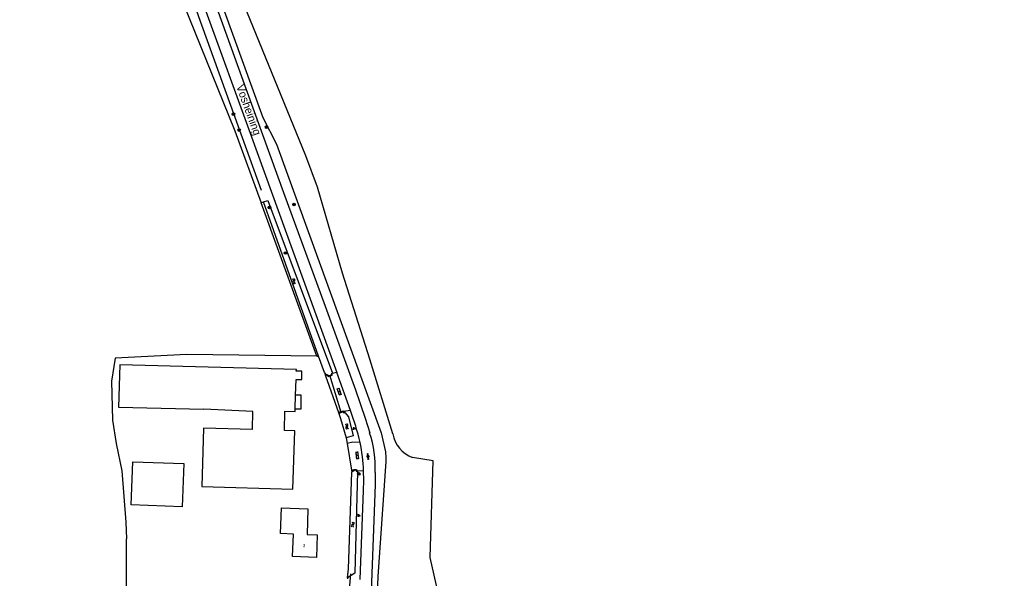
# Model space of a CAD drawing. Extents: x 124000 to 129000, y 395500 to 397503.
# Drawn here: x 125297.3 to 125607.1, y 396007.3 to 396181.7 of the extents above; entities that cross this region are included whole.
import ezdxf

# ---------------------------------------------------------------- set-up
doc = ezdxf.new("R2010")
doc.units = 0
for name, color, linetype in [('gg-afsc-hekwerk', 7, 'Continuous'), ('gg-anno-huisnummerreeks BGT', 7, 'Continuous'), ('gg-anno-openbare ruimte label', 7, 'Continuous'), ('gg-bbg-bijgebouw', 7, 'Continuous'), ('gg-bbg-gedigitaliseerde bijgebouw', 7, 'Continuous'), ('gg-bbg-hoofdgebouw', 7, 'Continuous'), ('gg-bbg-luifel en loopbrug', 7, 'Continuous'), ('gg-knt-bronhoudergrens', 7, 'Continuous'), ('gg-knt-verharding', 7, 'Continuous'), ('gg-kntw-bovenkant insteek waterloop', 7, 'Continuous'), ('gg-kntw-midden sloot', 7, 'Continuous'), ('gg-kwrk-duiker nz buis', 7, 'Continuous'), ('gg-kwrk-uitstroombak niveau min 01', 7, 'Continuous'), ('gt-grn-groengrens', 7, 'Continuous'), ('gt-grn-weggrens', 7, 'Continuous'), ('gt-symb-boom', 7, 'Continuous'), ('gt-symb-gesloten verharding', 7, 'Continuous'), ('gt-symb-groenvak', 7, 'Continuous'), ('gt-symb-klinker verharding', 7, 'Continuous'), ('gt-symb-watersymbool', 7, 'Continuous')]:
    doc.layers.add(name, color=color, linetype=linetype)

# ---------------------------------------------------------------- blocks, each defined once
blk = doc.blocks.new('gt0-BOOM')
at = {"layer": 'gt-symb-boom'}
for radius in [0.4, 0.2]:
    blk.add_circle((0, 0), radius, dxfattribs=at)
blk = doc.blocks.new('gt0-WA')
at = {"layer": 'gt-symb-watersymbool'}
for centre, start, end in [((-0.32, 0.02), 28.0725, 151.9275), ((0.43, 0.42), 208.0725, 331.9275), ((-0.32, -0.43), 28.0725, 151.9275), ((0.43, -0.03), 208.0725, 331.9275)]:
    blk.add_arc(centre, 0.425, start, end, dxfattribs=at)
blk = doc.blocks.new('gt0-KL1')
at = {"layer": 'gt-symb-klinker verharding'}
for p, q in [((-1.15, 0.3), (1.15, 0.3)), ((-1, -0.3), (-1, 0.3)), ((-0.5, 0.3), (-0.5, 0.45)), ((0, -0.3), (0, 0.3)), ((0.5, 0.3), (0.5, 0.45)), ((1, -0.3), (1, 0.3)), ((-1.15, -0.3), (1.15, -0.3)), ((-0.5, -0.45), (-0.5, -0.3)), ((0.5, -0.45), (0.5, -0.3))]:
    blk.add_line(p, q, dxfattribs=at)
blk = doc.blocks.new('gt0-GESVH1')
at = {"layer": 'gt-symb-gesloten verharding'}
for p, q in [((-0.99, -0.26), (0.01, 0.24)), ((0.01, -0.26), (-0.99, 0.24)), ((0.01, 0.24), (1.01, -0.26)), ((1.01, 0.24), (0.01, -0.26))]:
    blk.add_line(p, q, dxfattribs=at)
blk = doc.blocks.new('gt0-GRVAK')
at = {"layer": 'gt-symb-groenvak'}
for p, q in [((-0.11, 0.19), (-0.23, 0.24)), ((-0.18, 0.15), (0.09, 0.15)), ((-0.09, 0.21), (-0.16, 0.32)), ((-0.05, 0.21), (-0.05, 0.39)), ((0, 0.21), (0.06, 0.32)), ((0.01, 0.19), (0.13, 0.24)), ((0.26, -0.05), (0.2, 0.06)), ((0.3, -0.05), (0.3, 0.13)), ((0.35, -0.05), (0.41, 0.06)), ((-0.25, -0.23), (-0.36, -0.18)), ((-0.32, -0.26), (-0.05, -0.26)), ((-0.23, -0.21), (-0.29, -0.09)), ((-0.18, -0.2), (-0.18, -0.02)), ((-0.14, -0.21), (-0.07, -0.09)), ((-0.12, -0.23), (0, -0.18)), ((0.24, -0.07), (0.12, -0.02)), ((0.17, -0.11), (0.44, -0.11)), ((0.37, -0.07), (0.49, -0.02))]:
    blk.add_line(p, q, dxfattribs=at)

msp = doc.modelspace()

# ---------------------------------------------------------------- linework, layer by layer
at = {"layer": 'gg-afsc-hekwerk'}
for points in [[(125522.53, 396395.86), (125323.08, 396320.05), (125317.12, 396305.83), (125373.18, 396151.15), (125377.47, 396142.84), (125410.13, 396052.73), (125411.5, 396046.76), (125411.55, 396044.93)], [(125411.55, 396044.93), (125411.59, 396043.72), (125409.06, 396007.83), (125408.72, 396000)], [(125411.55, 396044.93), (125411.59, 396043.72), (125409.06, 396007.83), (125408.72, 396000)]]:
    msp.add_lwpolyline(points, dxfattribs=at)
at = {"layer": 'gg-bbg-bijgebouw'}
msp.add_line((125383.28, 396060.21), (125383.4, 396064.41), dxfattribs=at)
for points in [[(125383.4, 396064.41), (125383.54, 396069.33), (125385.32, 396069.3), (125385.37, 396071.91), (125383.61, 396071.94), (125383.62, 396072.48)], [(125382.54, 396035.08), (125383.12, 396053.31), (125379.88, 396053.41), (125380.01, 396059.41), (125383.25, 396059.31), (125383.28, 396060.21)]]:
    msp.add_lwpolyline(points, dxfattribs=at)
at = {"layer": 'gg-bbg-gedigitaliseerde bijgebouw'}
for p, q in [((125370.07, 396059.4), (125354.78, 396060.04)), ((125369.89, 396053.72), (125370.07, 396059.4)), ((125369.89, 396053.72), (125354.61, 396054.19))]:
    msp.add_line(p, q, dxfattribs=at)
for points in [[(125383.62, 396072.48), (125328.46, 396073.92), (125328.12, 396060.7), (125354.78, 396060.04)], [(125354.61, 396054.19), (125354.09, 396035.92), (125382.54, 396035.08)], [(125348.47, 396043.08), (125347.97, 396029.57), (125332.03, 396030.15), (125332.53, 396043.67), (125348.47, 396043.08)]]:
    msp.add_lwpolyline(points, dxfattribs=at)
at = {"layer": 'gg-bbg-hoofdgebouw'}
for points in [[(125389.95, 396013.8), (125382.4, 396014.03), (125382.7, 396021.09), (125378.66, 396021.26), (125378.99, 396029.29), (125387.2, 396028.95)], [(125387.2, 396028.95), (125386.96, 396020.91), (125390.15, 396020.81), (125389.95, 396013.8)]]:
    msp.add_lwpolyline(points, dxfattribs=at)
at = {"layer": 'gg-bbg-luifel en loopbrug'}
msp.add_lwpolyline([(125383.28, 396060.21), (125385.17, 396060.21), (125385.17, 396064.41), (125383.4, 396064.41)], dxfattribs=at)
at = {"layer": 'gg-knt-bronhoudergrens'}
for points in [[(125390.06, 396076.67), (125349.47, 396077.15), (125327.08, 396076.05), (125325.93, 396068.86), (125326.18, 396056.69), (125327.36, 396049.34), (125329.18, 396040.84), (125330.36, 396024.77), (125330.56, 396019.61)], [(125354.73, 395971.88), (125330.71, 395973.86), (125330.56, 396019.61)]]:
    msp.add_lwpolyline(points, dxfattribs=at)
at = {"layer": 'gg-knt-verharding'}
for p, q in [((125393.22, 396070.65), (125392.74, 396070.5)), ((125396.24, 396071.55), (125394.84, 396071.18)), ((125400.53, 396059.66), (125396.24, 396071.55)), ((125397.06, 396059.11), (125396.74, 396059.02)), ((125400.53, 396059.66), (125398.3, 396059.36)), ((125401.26, 396049.76), (125399.49, 396049.31)), ((125403.54, 396049.71), (125401.26, 396049.76)), ((125401.34, 396040.97), (125400.84, 396041.01)), ((125402.55, 396040.95), (125404.6, 396040.82))]:
    msp.add_line(p, q, dxfattribs=at)
for points in [[(125297.3, 396317.49), (125297.6, 396317.49), (125300.21, 396317.26), (125302.23, 396316.68), (125304.12, 396315.82), (125306.01, 396314.73), (125307.9, 396313.17), (125308.08, 396312.99), (125308.22, 396312.76), (125313.64, 396298.7), (125318.32, 396286.7), (125321.44, 396278.36), (125327.18, 396262.69), (125339.44, 396228.73), (125351.78, 396194.33), (125351.79, 396193.79), (125354.97, 396184.99), (125355.35, 396184.37), (125369.2, 396146.32), (125396.24, 396071.55)], [(125315.83, 396305.21), (125319.41, 396294.14), (125322.31, 396286.02), (125330.9, 396262.56), (125343.24, 396228.47), (125367.85, 396160.22), (125380.01, 396126.65), (125392.15, 396093.35), (125402.06, 396066.11), (125405.06, 396057.32), (125406.51, 396052.74)], [(125403.53, 396006.93), (125404.61, 396034.64), (125404.7, 396037.8), (125404.6, 396040.82)], [(125408.26, 396040.29), (125408.2, 396036.69), (125408.11, 396033.66), (125406.74, 395997.76), (125405.41, 395962.48), (125405, 395955.45)]]:
    msp.add_lwpolyline(points, dxfattribs=at)
for centre, radius, start, end in [((125314.77, 396028.27), 91.32, 13.5772, 20.1092), ((125371.13, 396041.39), 37.15, 358.295, 17.7757), ((125346.61, 396038.45), 58.03, 2.3403, 11.1804)]:
    msp.add_arc(centre, radius, start, end, dxfattribs=at)
at = {"layer": 'gg-kntw-bovenkant insteek waterloop'}
for p, q in [((125390.55, 396076.68), (125373.37, 396124.82)), ((125392.38, 396071.53), (125390.55, 396076.68)), ((125393.06, 396070.82), (125392.38, 396071.53)), ((125426.33, 396043.93), (125419.84, 396045.03)), ((125400.94, 396040.42), (125401.15, 396040.7))]:
    msp.add_line(p, q, dxfattribs=at)
for points in [[(125413.74, 396052.34), (125406.61, 396075.67), (125398.05, 396102.59), (125390.23, 396129.38), (125386.57, 396139.17), (125366.26, 396188.99), (125348.36, 396237.15), (125328.31, 396292.06)], [(125373.37, 396124.82), (125374.73, 396125.25), (125394.86, 396071.32)], [(125396.94, 396058.46), (125397.44, 396057.21), (125399.2, 396051.09)], [(125398.71, 396058.99), (125399.93, 396057.66), (125401.4, 396051.7), (125399.2, 396051.09)], [(125669.82, 395977.7), (125669.12, 395976.59), (125647.51, 395947.73), (125636.12, 395926.55), (125625.87, 395917.2), (125609.37, 395912.61), (125588.19, 395915.51), (125491.04, 395926.98), (125474.8, 395936.16), (125463.62, 395943.73), (125447.81, 395957.05), (125434.62, 395972.8), (125425.44, 396013.79), (125426.33, 396043.93)], [(125402.74, 396040.64), (125401.84, 396008.85), (125399.64, 396007.42)], [(125399.64, 396007.42), (125399.92, 396010.21), (125400.94, 396040.42)]]:
    msp.add_lwpolyline(points, dxfattribs=at)
msp.add_arc((125423.21, 396054.05), 9.63, 190.2327, 249.5263, dxfattribs=at)
at = {"layer": 'gg-kntw-midden sloot'}
msp.add_lwpolyline([(125372.74, 396128.37), (125353.15, 396182.63), (125350.67, 396189.91)], dxfattribs=at)
at = {"layer": 'gg-kwrk-duiker nz buis'}
for p, q in [((125397.65, 396059.06), (125394.04, 396070.66)), ((125399.97, 396001.3), (125400.6, 396008.64))]:
    msp.add_line(p, q, dxfattribs=at)
at = {"layer": 'gg-kwrk-uitstroombak niveau min 01'}
for p, q in [((125393.06, 396070.82), (125393.22, 396070.65)), ((125394.84, 396071.18), (125394.86, 396071.32)), ((125397.06, 396059.11), (125396.94, 396058.46)), ((125398.71, 396058.99), (125398.3, 396059.36)), ((125401.15, 396040.7), (125401.34, 396040.97)), ((125402.55, 396040.95), (125402.74, 396040.64))]:
    msp.add_line(p, q, dxfattribs=at)
for points in [[(125393.06, 396070.82), (125393.24, 396070.93), (125393.6, 396070.54), (125394.57, 396070.83), (125394.67, 396071.34), (125394.86, 396071.32)], [(125393.22, 396070.65), (125393.53, 396070.3), (125394.76, 396070.69), (125394.84, 396071.18)], [(125396.94, 396058.46), (125397.12, 396058.4), (125397.22, 396058.91), (125398.18, 396059.2), (125398.59, 396058.85), (125398.71, 396058.99)], [(125398.3, 396059.36), (125398.23, 396059.42), (125397.06, 396059.11)], [(125402.74, 396040.64), (125402.57, 396040.55), (125402.27, 396041.02), (125401.64, 396041), (125401.32, 396040.58), (125401.15, 396040.7)], [(125401.34, 396040.97), (125401.5, 396041.2), (125402.39, 396041.22), (125402.55, 396040.95)]]:
    msp.add_lwpolyline(points, dxfattribs=at)
at = {"layer": 'gt-grn-groengrens'}
for p, q in [((125372.61, 396124.57), (125373.37, 396124.82)), ((125390.06, 396076.67), (125372.61, 396124.57)), ((125390.06, 396076.67), (125390.55, 396076.68)), ((125392.38, 396071.53), (125392.74, 396070.5)), ((125396.74, 396059.02), (125396.94, 396058.46)), ((125399.2, 396051.09), (125399.49, 396049.31)), ((125400.84, 396041.01), (125400.94, 396040.42)), ((125399.64, 396007.42), (125399.61, 396007.13))]:
    msp.add_line(p, q, dxfattribs=at)
msp.add_lwpolyline([(125346.55, 396191.42), (125364.43, 396147.01), (125372.61, 396124.57)], dxfattribs=at)
at = {"layer": 'gt-grn-weggrens'}
for p, q in [((125392.74, 396070.5), (125396.74, 396059.02)), ((125399.49, 396049.31), (125400.84, 396041.01))]:
    msp.add_line(p, q, dxfattribs=at)

# ---------------------------------------------------------------- block references
at = {"layer": 'gt-symb-boom'}
for p in [(125363.97, 396152.21), (125365.74, 396147.26), (125374.33, 396148.15), (125375.21, 396123.09), (125382.89, 396124.01), (125380.24, 396108.86), (125403.14, 396039.86)]:
    msp.add_blockref('gt0-BOOM', p, dxfattribs=at)
at = {"layer": 'gt-symb-gesloten verharding', "rotation": 98.04906170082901}
msp.add_blockref('gt0-GESVH1', (125405.96, 396045.28), dxfattribs=at)
at = {"layer": 'gt-symb-groenvak'}
for p in [(125401.61, 396054.08), (125403.09, 396026.89)]:
    msp.add_blockref('gt0-GRVAK', p, dxfattribs=at)
at = {"layer": 'gt-symb-klinker verharding'}
for p, rotation in [((125396.97, 396065.59), -70.24210003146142), ((125402.59, 396045.66), -83.39396584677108)]:
    msp.add_blockref('gt0-KL1', p, dxfattribs=dict(at, rotation=rotation))
at = {"layer": 'gt-symb-watersymbool'}
for p, rotation in [((125382.86, 396100.08), -70.24210002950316), ((125399.38, 396054.73), -70.24210003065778), ((125401.23, 396024.09), -91.94925412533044)]:
    msp.add_blockref('gt0-WA', p, dxfattribs=dict(at, rotation=rotation))

# ---------------------------------------------------------------- texts
at = {"layer": 'gg-anno-huisnummerreeks BGT'}
msp.add_text('3', height=1, rotation=358.3, dxfattribs=at).set_placement((125385.65, 396016.99))
at = {"layer": 'gg-anno-openbare ruimte label'}
msp.add_text('Vosheining', height=2.5, rotation=289.9, dxfattribs=at).set_placement((125364.79, 396160.92))

doc.saveas('drawing.dxf')
